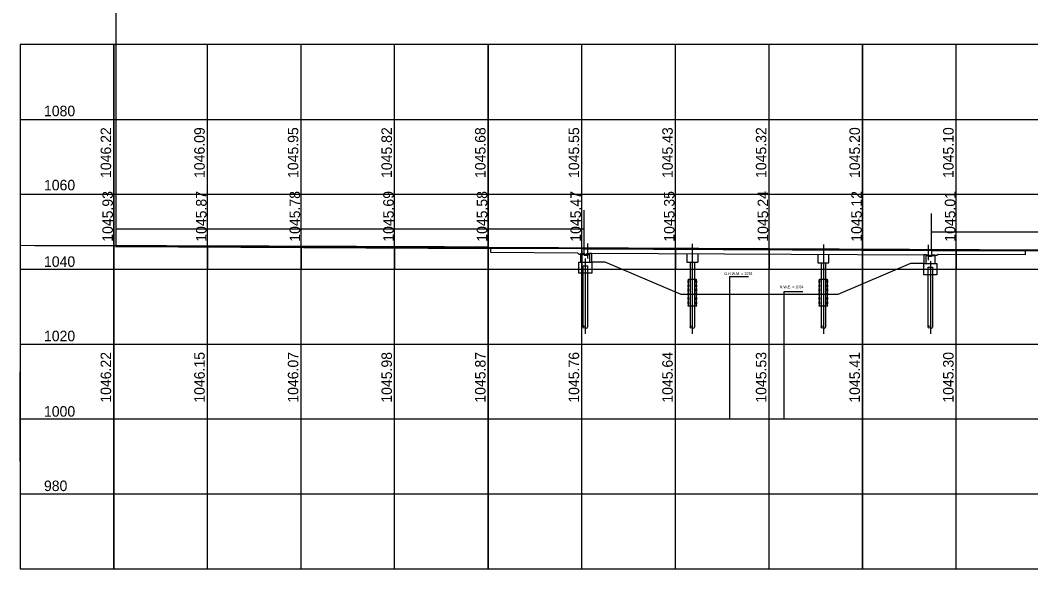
# Model space of a CAD drawing. Extents: x -2222 to 2066, y -217 to 964.
# Drawn here: x -1844.8 to -1574.9, y -68.1 to 78.3 of the extents above; entities that cross this region are included whole.
import ezdxf

# ---------------------------------------------------------------- set-up
doc = ezdxf.new("R2010")
doc.units = 0
for name, color, linetype in [('BR_P_Gen_Approach_Slab', 7, 'Continuous'), ('BR_P_Gen_Joint_Filler', 7, 'Continuous'), ('BR_P_Slab_Object', 7, 'Continuous'), ('BR_X_Gen_Approach_Slab', 7, 'Continuous'), ('BR_X_Slab_Object', 7, 'Continuous'), ('BR_X_Sub_Centerline', 7, 'Continuous'), ('BR_X_Sub_Deep_Centerline', 7, 'Continuous'), ('BR_X_Sub_Deep_Object', 7, 'Continuous'), ('BR_X_Sub_Object', 7, 'Continuous'), ('PF_X_Ground_Line', 7, 'Continuous'), ('SC_Scratch1', 7, 'Continuous'), ('SC_Scratch2', 7, 'Continuous'), ('SC_Scratch3', 7, 'Continuous'), ('XS_P_Pavt_Surface', 7, 'Continuous')]:
    doc.layers.add(name, color=color, linetype=linetype)

msp = doc.modelspace()

# ---------------------------------------------------------------- linework, layer by layer
at = {"layer": 'BR_P_Gen_Approach_Slab'}
for p, q in [((-1694.21, 17.26), (-1719.21, 17.4)), ((-1601.47, 16.83), (-1576.47, 16.77))]:
    msp.add_line(p, q, dxfattribs=at)
at = {"layer": 'BR_P_Gen_Joint_Filler'}
for points in [[(-1694.29, 17.41), (-1694.21, 17.41), (-1694.21, 17.24), (-1694.29, 17.24)], [(-1601.47, 16.98), (-1601.39, 16.98), (-1601.39, 16.81), (-1601.47, 16.81)]]:
    msp.add_lwpolyline(points, close=True, dxfattribs=at)
at = {"layer": 'BR_P_Slab_Object'}
for p, q in [((-1601.47, 16.98), (-1694.21, 17.41)), ((-1694.21, 17.41), (-1694.21, 17.26)), ((-1694.21, 17.26), (-1601.47, 16.83)), ((-1601.47, 16.83), (-1601.47, 16.98))]:
    msp.add_line(p, q, dxfattribs=at)
at = {"layer": 'BR_X_Gen_Approach_Slab'}
for points in [[(-1694.21, 17.32), (-1719.21, 17.44), (-1719.21, 16.36), (-1696.02, 16.25), (-1695.65, 15.88), (-1695.07, 15.88)], [(-1601.47, 16.9), (-1576.47, 16.78), (-1576.47, 15.7), (-1599.69, 15.81), (-1600.03, 15.47), (-1600.6, 15.47)]]:
    msp.add_lwpolyline(points, dxfattribs=at)
at = {"layer": 'BR_X_Slab_Object'}
for p, q in [((-1694.21, 16.08), (-1694.21, 17.32)), ((-1694.21, 17.32), (-1601.47, 16.9)), ((-1601.47, 16.9), (-1601.47, 15.68))]:
    msp.add_line(p, q, dxfattribs=at)
at = {"layer": 'BR_X_Sub_Centerline'}
for p, q in [((-1665.34, 18.63), (-1665.34, -5.41)), ((-1630.34, 18.47), (-1630.34, -5.41)), ((-1602.34, 18.34), (-1602.34, 14.27)), ((-1601.76, 14.03), (-1601.76, -5.41))]:
    msp.add_line(p, q, dxfattribs=at)
at = {"layer": 'BR_X_Sub_Deep_Centerline'}
for p, q in [((-1693.34, 18.75), (-1693.34, 14.68)), ((-1693.92, 14.68), (-1693.92, -5.41))]:
    msp.add_line(p, q, dxfattribs=at)
at = {"layer": 'BR_X_Sub_Deep_Object'}
for p, q in [((-1665.92, 13.69), (-1665.92, -3.6)), ((-1664.76, 13.69), (-1664.76, -3.6)), ((-1630.92, 13.53), (-1630.92, -3.6)), ((-1629.76, 13.53), (-1629.76, -3.6)), ((-1664.34, 9.06), (-1666.34, 9.06)), ((-1629.34, 9.06), (-1631.34, 9.06))]:
    msp.add_line(p, q, dxfattribs=at)
for points in [[(-1694.5, -3.6), (-1694.5, 12.76), (-1693.34, 12.76), (-1693.34, -3.6)], [(-1602.34, -3.6), (-1602.34, 12.36), (-1601.17, 12.36), (-1601.17, -3.6)], [(-1666.34, 9.06), (-1666.52, 9.03), (-1666.52, 8.97), (-1666.34, 8.93), (-1666.34, 8.87), (-1666.52, 8.84), (-1666.52, 8.77), (-1666.34, 8.74), (-1666.34, 8.68), (-1666.52, 8.65), (-1666.52, 8.58), (-1666.34, 8.55), (-1666.34, 8.48), (-1666.52, 8.45), (-1666.52, 8.39), (-1666.34, 8.35), (-1666.34, 8.29), (-1666.52, 8.26), (-1666.52, 8.19), (-1666.34, 8.16), (-1666.34, 8.1), (-1666.52, 8.07), (-1666.52, 8), (-1666.34, 7.97), (-1666.34, 7.91), (-1666.52, 7.87), (-1666.52, 7.81), (-1666.34, 7.77), (-1666.34, 7.71), (-1666.52, 7.68), (-1666.52, 7.61), (-1666.34, 7.58), (-1666.34, 7.52), (-1666.52, 7.49), (-1666.52, 7.42), (-1666.34, 7.39), (-1666.34, 7.33), (-1666.52, 7.29), (-1666.52, 7.23), (-1666.34, 7.19), (-1666.34, 7.13), (-1666.52, 7.1), (-1666.52, 7.03), (-1666.34, 7), (-1666.34, 6.94), (-1666.52, 6.91), (-1666.52, 6.84), (-1666.34, 6.81), (-1666.34, 6.75), (-1666.52, 6.71), (-1666.52, 6.65), (-1666.34, 6.61), (-1666.34, 6.55), (-1666.52, 6.52), (-1666.52, 6.45), (-1666.34, 6.42), (-1666.34, 6.36), (-1666.52, 6.33), (-1666.52, 6.26), (-1666.34, 6.23), (-1666.34, 6.17), (-1666.52, 6.13), (-1666.52, 6.07), (-1666.34, 6.03), (-1666.34, 5.97), (-1666.52, 5.94), (-1666.52, 5.87), (-1666.34, 5.84), (-1666.34, 5.78), (-1666.52, 5.75), (-1666.52, 5.68), (-1666.34, 5.65), (-1666.34, 5.59), (-1666.52, 5.55), (-1666.52, 5.49), (-1666.34, 5.45), (-1666.34, 5.39), (-1666.52, 5.36), (-1666.52, 5.29), (-1666.34, 5.26), (-1666.34, 5.2), (-1666.52, 5.17), (-1666.52, 5.1), (-1666.34, 5.07), (-1666.34, 5.01), (-1666.52, 4.97), (-1666.52, 4.91), (-1666.34, 4.87), (-1666.34, 4.81), (-1666.52, 4.78), (-1666.52, 4.71), (-1666.34, 4.68), (-1666.34, 4.62), (-1666.52, 4.59), (-1666.52, 4.52), (-1666.34, 4.49), (-1666.34, 4.43), (-1666.52, 4.39), (-1666.52, 4.33), (-1666.34, 4.29), (-1666.34, 4.23), (-1666.52, 4.2), (-1666.52, 4.13), (-1666.34, 4.1), (-1666.34, 4.04), (-1666.52, 4.01), (-1666.52, 3.94), (-1666.34, 3.91), (-1666.34, 3.85), (-1666.52, 3.81), (-1666.52, 3.75), (-1666.34, 3.72), (-1666.34, 3.65), (-1666.52, 3.62), (-1666.52, 3.55), (-1666.34, 3.52), (-1666.34, 3.46), (-1666.52, 3.43), (-1666.52, 3.36), (-1666.34, 3.33), (-1666.34, 3.27), (-1666.52, 3.23), (-1666.52, 3.17), (-1666.34, 3.14), (-1666.34, 3.07), (-1666.52, 3.04), (-1666.52, 2.97), (-1666.34, 2.94), (-1666.34, 2.88), (-1666.52, 2.85), (-1666.52, 2.78), (-1666.34, 2.75), (-1666.34, 2.69), (-1666.52, 2.65), (-1666.52, 2.59), (-1666.34, 2.56), (-1666.34, 2.49), (-1666.52, 2.46), (-1666.52, 2.39), (-1666.34, 2.36), (-1666.34, 2.3), (-1666.52, 2.27), (-1666.52, 2.2), (-1666.34, 2.17), (-1666.34, 2.11), (-1666.52, 2.07), (-1666.52, 2.06), (-1664.16, 2.06), (-1664.16, 2.07), (-1664.34, 2.11), (-1664.34, 2.17), (-1664.16, 2.2), (-1664.16, 2.27), (-1664.34, 2.3), (-1664.34, 2.36), (-1664.16, 2.39), (-1664.16, 2.46), (-1664.34, 2.49), (-1664.34, 2.56), (-1664.16, 2.59), (-1664.16, 2.65), (-1664.34, 2.69), (-1664.34, 2.75), (-1664.16, 2.78), (-1664.16, 2.85), (-1664.34, 2.88), (-1664.34, 2.94), (-1664.16, 2.97), (-1664.16, 3.04), (-1664.34, 3.07), (-1664.34, 3.14), (-1664.16, 3.17), (-1664.16, 3.23), (-1664.34, 3.27), (-1664.34, 3.33), (-1664.16, 3.36), (-1664.16, 3.43), (-1664.34, 3.46), (-1664.34, 3.52), (-1664.16, 3.55), (-1664.16, 3.62), (-1664.34, 3.65), (-1664.34, 3.72), (-1664.16, 3.75), (-1664.16, 3.81), (-1664.34, 3.85), (-1664.34, 3.91), (-1664.16, 3.94), (-1664.16, 4.01), (-1664.34, 4.04), (-1664.34, 4.1), (-1664.16, 4.13), (-1664.16, 4.2), (-1664.34, 4.23), (-1664.34, 4.29), (-1664.16, 4.33), (-1664.16, 4.39), (-1664.34, 4.43), (-1664.34, 4.49), (-1664.16, 4.52), (-1664.16, 4.59), (-1664.34, 4.62), (-1664.34, 4.68), (-1664.16, 4.71), (-1664.16, 4.78), (-1664.34, 4.81), (-1664.34, 4.87), (-1664.16, 4.91), (-1664.16, 4.97), (-1664.34, 5.01), (-1664.34, 5.07), (-1664.16, 5.1), (-1664.16, 5.17), (-1664.34, 5.2), (-1664.34, 5.26), (-1664.16, 5.29), (-1664.16, 5.36), (-1664.34, 5.39), (-1664.34, 5.45), (-1664.16, 5.49), (-1664.16, 5.55), (-1664.34, 5.59), (-1664.34, 5.65), (-1664.16, 5.68), (-1664.16, 5.75), (-1664.34, 5.78), (-1664.34, 5.84), (-1664.16, 5.87), (-1664.16, 5.94), (-1664.34, 5.97), (-1664.34, 6.03), (-1664.16, 6.07), (-1664.16, 6.13), (-1664.34, 6.17), (-1664.34, 6.23), (-1664.16, 6.26), (-1664.16, 6.33), (-1664.34, 6.36), (-1664.34, 6.42), (-1664.16, 6.45), (-1664.16, 6.52), (-1664.34, 6.55), (-1664.34, 6.61), (-1664.16, 6.65), (-1664.16, 6.71), (-1664.34, 6.75), (-1664.34, 6.81), (-1664.16, 6.84), (-1664.16, 6.91), (-1664.34, 6.94), (-1664.34, 7), (-1664.16, 7.03), (-1664.16, 7.1), (-1664.34, 7.13), (-1664.34, 7.19), (-1664.16, 7.23), (-1664.16, 7.29), (-1664.34, 7.33), (-1664.34, 7.39), (-1664.16, 7.42), (-1664.16, 7.49), (-1664.34, 7.52), (-1664.34, 7.58), (-1664.16, 7.61), (-1664.16, 7.68), (-1664.34, 7.71), (-1664.34, 7.77), (-1664.16, 7.81), (-1664.16, 7.87), (-1664.34, 7.91), (-1664.34, 7.97), (-1664.16, 8), (-1664.16, 8.07), (-1664.34, 8.1), (-1664.34, 8.16), (-1664.16, 8.19), (-1664.16, 8.26), (-1664.34, 8.29), (-1664.34, 8.35), (-1664.16, 8.39), (-1664.16, 8.45), (-1664.34, 8.48), (-1664.34, 8.55), (-1664.16, 8.58), (-1664.16, 8.65), (-1664.34, 8.68), (-1664.34, 8.74), (-1664.16, 8.77), (-1664.16, 8.84), (-1664.34, 8.87), (-1664.34, 8.93), (-1664.16, 8.97), (-1664.16, 9.03), (-1664.34, 9.06)], [(-1666.34, 9.06), (-1665.92, 9.15), (-1664.76, 9.15), (-1664.34, 9.06)], [(-1631.34, 9.06), (-1631.52, 9.03), (-1631.52, 8.97), (-1631.34, 8.93), (-1631.34, 8.87), (-1631.52, 8.84), (-1631.52, 8.77), (-1631.34, 8.74), (-1631.34, 8.68), (-1631.52, 8.65), (-1631.52, 8.58), (-1631.34, 8.55), (-1631.34, 8.48), (-1631.52, 8.45), (-1631.52, 8.39), (-1631.34, 8.35), (-1631.34, 8.29), (-1631.52, 8.26), (-1631.52, 8.19), (-1631.34, 8.16), (-1631.34, 8.1), (-1631.52, 8.07), (-1631.52, 8), (-1631.34, 7.97), (-1631.34, 7.91), (-1631.52, 7.87), (-1631.52, 7.81), (-1631.34, 7.77), (-1631.34, 7.71), (-1631.52, 7.68), (-1631.52, 7.61), (-1631.34, 7.58), (-1631.34, 7.52), (-1631.52, 7.49), (-1631.52, 7.42), (-1631.34, 7.39), (-1631.34, 7.33), (-1631.52, 7.29), (-1631.52, 7.23), (-1631.34, 7.19), (-1631.34, 7.13), (-1631.52, 7.1), (-1631.52, 7.03), (-1631.34, 7), (-1631.34, 6.94), (-1631.52, 6.91), (-1631.52, 6.84), (-1631.34, 6.81), (-1631.34, 6.75), (-1631.52, 6.71), (-1631.52, 6.65), (-1631.34, 6.61), (-1631.34, 6.55), (-1631.52, 6.52), (-1631.52, 6.45), (-1631.34, 6.42), (-1631.34, 6.36), (-1631.52, 6.33), (-1631.52, 6.26), (-1631.34, 6.23), (-1631.34, 6.17), (-1631.52, 6.13), (-1631.52, 6.07), (-1631.34, 6.03), (-1631.34, 5.97), (-1631.52, 5.94), (-1631.52, 5.87), (-1631.34, 5.84), (-1631.34, 5.78), (-1631.52, 5.75), (-1631.52, 5.68), (-1631.34, 5.65), (-1631.34, 5.59), (-1631.52, 5.55), (-1631.52, 5.49), (-1631.34, 5.45), (-1631.34, 5.39), (-1631.52, 5.36), (-1631.52, 5.29), (-1631.34, 5.26), (-1631.34, 5.2), (-1631.52, 5.17), (-1631.52, 5.1), (-1631.34, 5.07), (-1631.34, 5.01), (-1631.52, 4.97), (-1631.52, 4.91), (-1631.34, 4.87), (-1631.34, 4.81), (-1631.52, 4.78), (-1631.52, 4.71), (-1631.34, 4.68), (-1631.34, 4.62), (-1631.52, 4.59), (-1631.52, 4.52), (-1631.34, 4.49), (-1631.34, 4.43), (-1631.52, 4.39), (-1631.52, 4.33), (-1631.34, 4.29), (-1631.34, 4.23), (-1631.52, 4.2), (-1631.52, 4.13), (-1631.34, 4.1), (-1631.34, 4.04), (-1631.52, 4.01), (-1631.52, 3.94), (-1631.34, 3.91), (-1631.34, 3.85), (-1631.52, 3.81), (-1631.52, 3.75), (-1631.34, 3.72), (-1631.34, 3.65), (-1631.52, 3.62), (-1631.52, 3.55), (-1631.34, 3.52), (-1631.34, 3.46), (-1631.52, 3.43), (-1631.52, 3.36), (-1631.34, 3.33), (-1631.34, 3.27), (-1631.52, 3.23), (-1631.52, 3.17), (-1631.34, 3.14), (-1631.34, 3.07), (-1631.52, 3.04), (-1631.52, 2.97), (-1631.34, 2.94), (-1631.34, 2.88), (-1631.52, 2.85), (-1631.52, 2.78), (-1631.34, 2.75), (-1631.34, 2.69), (-1631.52, 2.65), (-1631.52, 2.59), (-1631.34, 2.56), (-1631.34, 2.49), (-1631.52, 2.46), (-1631.52, 2.39), (-1631.34, 2.36), (-1631.34, 2.3), (-1631.52, 2.27), (-1631.52, 2.2), (-1631.34, 2.17), (-1631.34, 2.11), (-1631.52, 2.07), (-1631.52, 2.06), (-1629.16, 2.06), (-1629.16, 2.07), (-1629.34, 2.11), (-1629.34, 2.17), (-1629.16, 2.2), (-1629.16, 2.27), (-1629.34, 2.3), (-1629.34, 2.36), (-1629.16, 2.39), (-1629.16, 2.46), (-1629.34, 2.49), (-1629.34, 2.56), (-1629.16, 2.59), (-1629.16, 2.65), (-1629.34, 2.69), (-1629.34, 2.75), (-1629.16, 2.78), (-1629.16, 2.85), (-1629.34, 2.88), (-1629.34, 2.94), (-1629.16, 2.97), (-1629.16, 3.04), (-1629.34, 3.07), (-1629.34, 3.14), (-1629.16, 3.17), (-1629.16, 3.23), (-1629.34, 3.27), (-1629.34, 3.33), (-1629.16, 3.36), (-1629.16, 3.43), (-1629.34, 3.46), (-1629.34, 3.52), (-1629.16, 3.55), (-1629.16, 3.62), (-1629.34, 3.65), (-1629.34, 3.72), (-1629.16, 3.75), (-1629.16, 3.81), (-1629.34, 3.85), (-1629.34, 3.91), (-1629.16, 3.94), (-1629.16, 4.01), (-1629.34, 4.04), (-1629.34, 4.1), (-1629.16, 4.13), (-1629.16, 4.2), (-1629.34, 4.23), (-1629.34, 4.29), (-1629.16, 4.33), (-1629.16, 4.39), (-1629.34, 4.43), (-1629.34, 4.49), (-1629.16, 4.52), (-1629.16, 4.59), (-1629.34, 4.62), (-1629.34, 4.68), (-1629.16, 4.71), (-1629.16, 4.78), (-1629.34, 4.81), (-1629.34, 4.87), (-1629.16, 4.91), (-1629.16, 4.97), (-1629.34, 5.01), (-1629.34, 5.07), (-1629.16, 5.1), (-1629.16, 5.17), (-1629.34, 5.2), (-1629.34, 5.26), (-1629.16, 5.29), (-1629.16, 5.36), (-1629.34, 5.39), (-1629.34, 5.45), (-1629.16, 5.49), (-1629.16, 5.55), (-1629.34, 5.59), (-1629.34, 5.65), (-1629.16, 5.68), (-1629.16, 5.75), (-1629.34, 5.78), (-1629.34, 5.84), (-1629.16, 5.87), (-1629.16, 5.94), (-1629.34, 5.97), (-1629.34, 6.03), (-1629.16, 6.07), (-1629.16, 6.13), (-1629.34, 6.17), (-1629.34, 6.23), (-1629.16, 6.26), (-1629.16, 6.33), (-1629.34, 6.36), (-1629.34, 6.42), (-1629.16, 6.45), (-1629.16, 6.52), (-1629.34, 6.55), (-1629.34, 6.61), (-1629.16, 6.65), (-1629.16, 6.71), (-1629.34, 6.75), (-1629.34, 6.81), (-1629.16, 6.84), (-1629.16, 6.91), (-1629.34, 6.94), (-1629.34, 7), (-1629.16, 7.03), (-1629.16, 7.1), (-1629.34, 7.13), (-1629.34, 7.19), (-1629.16, 7.23), (-1629.16, 7.29), (-1629.34, 7.33), (-1629.34, 7.39), (-1629.16, 7.42), (-1629.16, 7.49), (-1629.34, 7.52), (-1629.34, 7.58), (-1629.16, 7.61), (-1629.16, 7.68), (-1629.34, 7.71), (-1629.34, 7.77), (-1629.16, 7.81), (-1629.16, 7.87), (-1629.34, 7.91), (-1629.34, 7.97), (-1629.16, 8), (-1629.16, 8.07), (-1629.34, 8.1), (-1629.34, 8.16), (-1629.16, 8.19), (-1629.16, 8.26), (-1629.34, 8.29), (-1629.34, 8.35), (-1629.16, 8.39), (-1629.16, 8.45), (-1629.34, 8.48), (-1629.34, 8.55), (-1629.16, 8.58), (-1629.16, 8.65), (-1629.34, 8.68), (-1629.34, 8.74), (-1629.16, 8.77), (-1629.16, 8.84), (-1629.34, 8.87), (-1629.34, 8.93), (-1629.16, 8.97), (-1629.16, 9.03), (-1629.34, 9.06)], [(-1631.34, 9.06), (-1630.92, 9.15), (-1629.76, 9.15), (-1629.34, 9.06)]]:
    msp.add_lwpolyline(points, dxfattribs=at)
for centre in [(-1694.21, -3.6), (-1665.63, -3.6), (-1630.63, -3.6), (-1602.05, -3.6)]:
    msp.add_circle(centre, 0.292, dxfattribs=at)
for centre in [(-1693.63, -3.6), (-1665.05, -3.6), (-1630.05, -3.6), (-1601.47, -3.6)]:
    msp.add_arc(centre, 0.292, 180, 0, dxfattribs=at)
at = {"layer": 'BR_X_Sub_Object'}
for p, q in [((-1692.19, 16.09), (-1603.49, 15.68)), ((-1666.78, 15.97), (-1666.78, 13.69)), ((-1666.78, 13.69), (-1663.9, 13.69)), ((-1663.9, 15.95), (-1663.9, 13.69)), ((-1631.78, 15.81), (-1631.78, 13.53)), ((-1631.78, 13.53), (-1628.9, 13.53)), ((-1628.9, 13.53), (-1628.9, 15.79)), ((-1602.91, 13.36), (-1602.91, 15.68)), ((-1602.91, 15.68), (-1602.19, 15.68)), ((-1602.19, 15.68), (-1602.19, 15.47)), ((-1602.19, 15.47), (-1601.47, 15.47)), ((-1601.47, 15.47), (-1601.47, 15.68)), ((-1601.47, 15.68), (-1600.6, 15.68)), ((-1600.6, 15.68), (-1600.6, 13.36))]:
    msp.add_line(p, q, dxfattribs=at)
for points in [[(-1695.65, 13.76), (-1692.19, 13.76), (-1692.19, 10.76), (-1695.65, 10.76)], [(-1603.49, 13.36), (-1600.03, 13.36), (-1600.03, 10.36), (-1603.49, 10.36)]]:
    msp.add_lwpolyline(points, close=True, dxfattribs=at)
for points in [[(-1695.07, 13.76), (-1695.07, 16.08), (-1694.21, 16.08), (-1694.21, 15.88), (-1693.49, 15.88), (-1693.49, 16.08), (-1692.77, 16.08), (-1692.77, 13.76)], [(-1692.19, 13.76), (-1692.19, 16.08), (-1692.77, 16.08)], [(-1602.91, 15.68), (-1603.49, 15.68), (-1603.49, 13.36)]]:
    msp.add_lwpolyline(points, dxfattribs=at)
at = {"layer": 'PF_X_Ground_Line'}
msp.add_line((-1719.84, 17.73), (-1569.84, 17.04), dxfattribs=at)
msp.add_lwpolyline([(-1603.49, 13.36), (-1607.1, 13.36), (-1626.48, 5.06), (-1668.27, 5.06), (-1688.58, 13.76), (-1692.19, 13.76)], dxfattribs=at)
msp.add_arc((-1928.93, -45436.94), 45455.15, 89.736441, 89.894003, dxfattribs=at)
at = {"layer": 'SC_Scratch1'}
for p, q in [((-1844.84, 71.86), (-1844.84, -68.14)), ((-1394.84, 71.86), (-1844.84, 71.86)), ((-1819.84, -68.14), (-1819.84, 71.86)), ((-1794.84, -68.14), (-1794.84, 71.86)), ((-1769.84, -68.14), (-1769.84, 71.86)), ((-1744.84, -68.14), (-1744.84, 71.86)), ((-1719.84, -68.14), (-1719.84, 71.86)), ((-1694.84, -68.14), (-1694.84, 71.86)), ((-1669.84, -68.14), (-1669.84, 71.86)), ((-1644.84, -68.14), (-1644.84, 71.86)), ((-1619.84, -68.14), (-1619.84, 71.86)), ((-1594.84, -68.14), (-1594.84, 71.86)), ((-1844.84, 51.86), (-1394.84, 51.86)), ((-1844.84, 31.86), (-1394.84, 31.86)), ((-1819.21, 17.7), (-1819.21, 27.6)), ((-1694.21, 17.41), (-1694.21, 27.6)), ((-1601.47, 16.83), (-1601.47, 26.74)), ((-1819.21, 22.65), (-1694.21, 22.65)), ((-1601.47, 21.79), (-1476.47, 21.79)), ((-1694.05, 17.32), (-1694.05, 17.61)), ((-1844.84, 11.86), (-1394.84, 11.86)), ((-1655.35, -28.14), (-1655.35, 9.86)), ((-1655.35, 9.86), (-1650.35, 9.86)), ((-1640.84, -28.14), (-1640.84, 5.86)), ((-1640.84, 5.86), (-1635.84, 5.86)), ((-1844.84, -8.14), (-1394.84, -8.14)), ((-1844.84, -39.52), (-1844.84, -15.55)), ((-1844.84, -28.14), (-1394.84, -28.14)), ((-1844.84, -48.14), (-1394.84, -48.14)), ((-1844.84, -68.14), (-1394.84, -68.14))]:
    msp.add_line(p, q, dxfattribs=at)
for points in [[(-1695.07, 15.81), (-1694.21, 15.81), (-1694.21, 15.61), (-1693.49, 15.61), (-1693.49, 15.81), (-1692.77, 15.81)], [(-1600.6, 15.41), (-1601.47, 15.41), (-1601.47, 15.2), (-1602.19, 15.2), (-1602.19, 15.41), (-1602.91, 15.41)]]:
    msp.add_lwpolyline(points, dxfattribs=at)
at = {"layer": 'SC_Scratch2'}
for p, q in [((-1819.84, 11.86), (-1819.84, 18.08)), ((-1794.84, 17.95), (-1794.84, 11.86)), ((-1769.84, 11.86), (-1769.84, 17.81)), ((-1744.84, 17.68), (-1744.84, 11.86)), ((-1719.84, 11.86), (-1719.84, 17.55)), ((-1694.84, 17.41), (-1694.84, 11.86)), ((-1669.84, 11.86), (-1669.84, 17.29)), ((-1644.84, 17.18), (-1644.84, 11.86)), ((-1619.84, 11.86), (-1619.84, 17.06)), ((-1594.84, 16.96), (-1594.84, 11.86)), ((-1692.19, 13.76), (-1692.19, 11.86)), ((-1665.34, 15.96), (-1665.34, 13.69)), ((-1630.34, 15.8), (-1630.34, 13.53)), ((-1630.34, 15.8), (-1630.34, 13.53)), ((-1603.49, 11.86), (-1603.49, 13.36))]:
    msp.add_line(p, q, dxfattribs=at)
at = {"layer": 'SC_Scratch3'}
for p, q in [((-1819.21, 18.08), (-1819.21, 928.19)), ((-1819.84, 71.86), (-1819.84, -68.14)), ((-1719.84, 71.86), (-1719.84, -68.14)), ((-1619.84, 71.86), (-1619.84, -68.14)), ((-1819.84, 18.08), (-1819.84, 11.86)), ((-1794.84, 18.02), (-1794.84, 11.86)), ((-1769.84, 17.94), (-1769.84, 11.86)), ((-1744.84, 17.84), (-1744.84, 11.86)), ((-1719.84, 17.73), (-1719.84, 11.86)), ((-1694.84, 17.62), (-1694.84, 11.86)), ((-1669.84, 17.5), (-1669.84, 11.86)), ((-1644.84, 17.39), (-1644.84, 11.86)), ((-1619.84, 17.27), (-1619.84, 11.86)), ((-1594.84, 17.16), (-1594.84, 11.86))]:
    msp.add_line(p, q, dxfattribs=at)
for points in [[(-1694.4, 17.41), (-1694.21, 17.41), (-1694.21, 17.32), (-1694.4, 17.32), (-1694.21, 17.32), (-1694.21, 17.26), (-1694.4, 17.26)], [(-1601.28, 16.98), (-1601.47, 16.98), (-1601.47, 16.9), (-1601.28, 16.9), (-1601.47, 16.9), (-1601.47, 16.83), (-1601.28, 16.83)]]:
    msp.add_lwpolyline(points, dxfattribs=at)
at = {"layer": 'XS_P_Pavt_Surface'}
for p, q in [((-1694.21, 17.41), (-1819.21, 18.08)), ((-1819.21, 18.08), (-1819.21, 17.94)), ((-1819.21, 17.94), (-1719.21, 17.4))]:
    msp.add_line(p, q, dxfattribs=at)
msp.add_lwpolyline([(-1601.47, 16.98), (-1476.47, 16.67), (-1476.47, 16.52), (-1576.47, 16.77)], dxfattribs=at)

# ---------------------------------------------------------------- texts
at = {"layer": 'SC_Scratch1'}
for s, height, p in [('1080', 2.8, (-1838.49, 52.69)), ('1060', 2.8, (-1838.49, 32.9)), ('1040', 2.8, (-1838.49, 12.48)), ('O.H.W.M. = 1038', 0.7, (-1656.79, 10.32)), ('N.W.E. = 1034', 0.7, (-1641.97, 6.77)), ('1020', 2.8, (-1838.49, -7.38)), ('1000', 2.8, (-1838.49, -27.52)), ('980', 2.8, (-1838.49, -47.39))]:
    msp.add_text(s, height=height, dxfattribs=at).set_placement(p)
for s, p in [('1046.22', (-1820.56, 36.21)), ('1046.09', (-1795.56, 36.21)), ('1045.95', (-1770.56, 36.21)), ('1045.82', (-1745.56, 36.21)), ('1045.68', (-1720.56, 36.21)), ('1045.55', (-1695.56, 36.21)), ('1045.43', (-1670.56, 36.21)), ('1045.32', (-1645.56, 36.21)), ('1045.20', (-1620.56, 36.21)), ('1045.10', (-1595.56, 36.21)), ('1045.93', (-1820.09, 19.18)), ('1045.87', (-1795.09, 19.18)), ('1045.78', (-1770.09, 19.18)), ('1045.69', (-1745.09, 19.18)), ('1045.58', (-1720.09, 19.18)), ('1045.47', (-1695.09, 19.18)), ('1045.35', (-1670.09, 19.18)), ('1045.24', (-1645.09, 19.18)), ('1045.12', (-1620.09, 19.18)), ('1045.01', (-1595.09, 19.18)), ('1046.22', (-1820.56, -23.79)), ('1046.15', (-1795.56, -23.79)), ('1046.07', (-1770.56, -23.79)), ('1045.98', (-1745.56, -23.79)), ('1045.87', (-1720.56, -23.79)), ('1045.76', (-1695.56, -23.79)), ('1045.64', (-1670.56, -23.79)), ('1045.53', (-1645.56, -23.79)), ('1045.41', (-1620.56, -23.79)), ('1045.30', (-1595.56, -23.79))]:
    msp.add_text(s, height=2.8, rotation=90, dxfattribs=at).set_placement(p)

doc.saveas('drawing.dxf')
